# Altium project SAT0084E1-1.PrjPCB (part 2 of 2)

## Sheet SAT0084E1-1_Backend.SchDoc: Class-D Amplifier
size 431 x 279 mm; Date: Not shown in title block; ApprovedBy: Not shown in title block; CheckedBy: Not shown in title block; Author: Not shown in title block; CompanyName: Not shown in title block; DrawnBy: Viktor Schneigelberger; Engineer: Not shown in title block; Organization: Not shown in title block; Address1: Not shown in title block; Address2: Not shown in title block; Address3: Not shown in title block; Address4: Not shown in title block; DocumentNumber: 6; Revision: Use project parameter SCH_Rev; SheetNumber: 6; SheetTotal: 7; PageSetup: Record=PageOptions|CenterHorizontal=True|CenterVertical=True|PrintScale=1.00|XCorrection=1.00|YCorrection=1.00|PrintKind=0|BorderSize=5000000|LeftOffset=0|BottomOffset=0|Orientation=2|PaperLength=1000|PaperWidth=1000|Scale=100|PaperSource=15|PrintQuality=600|MediaType=1|DitherType=10|PaperKind=Letter|PrintScaleMode=1
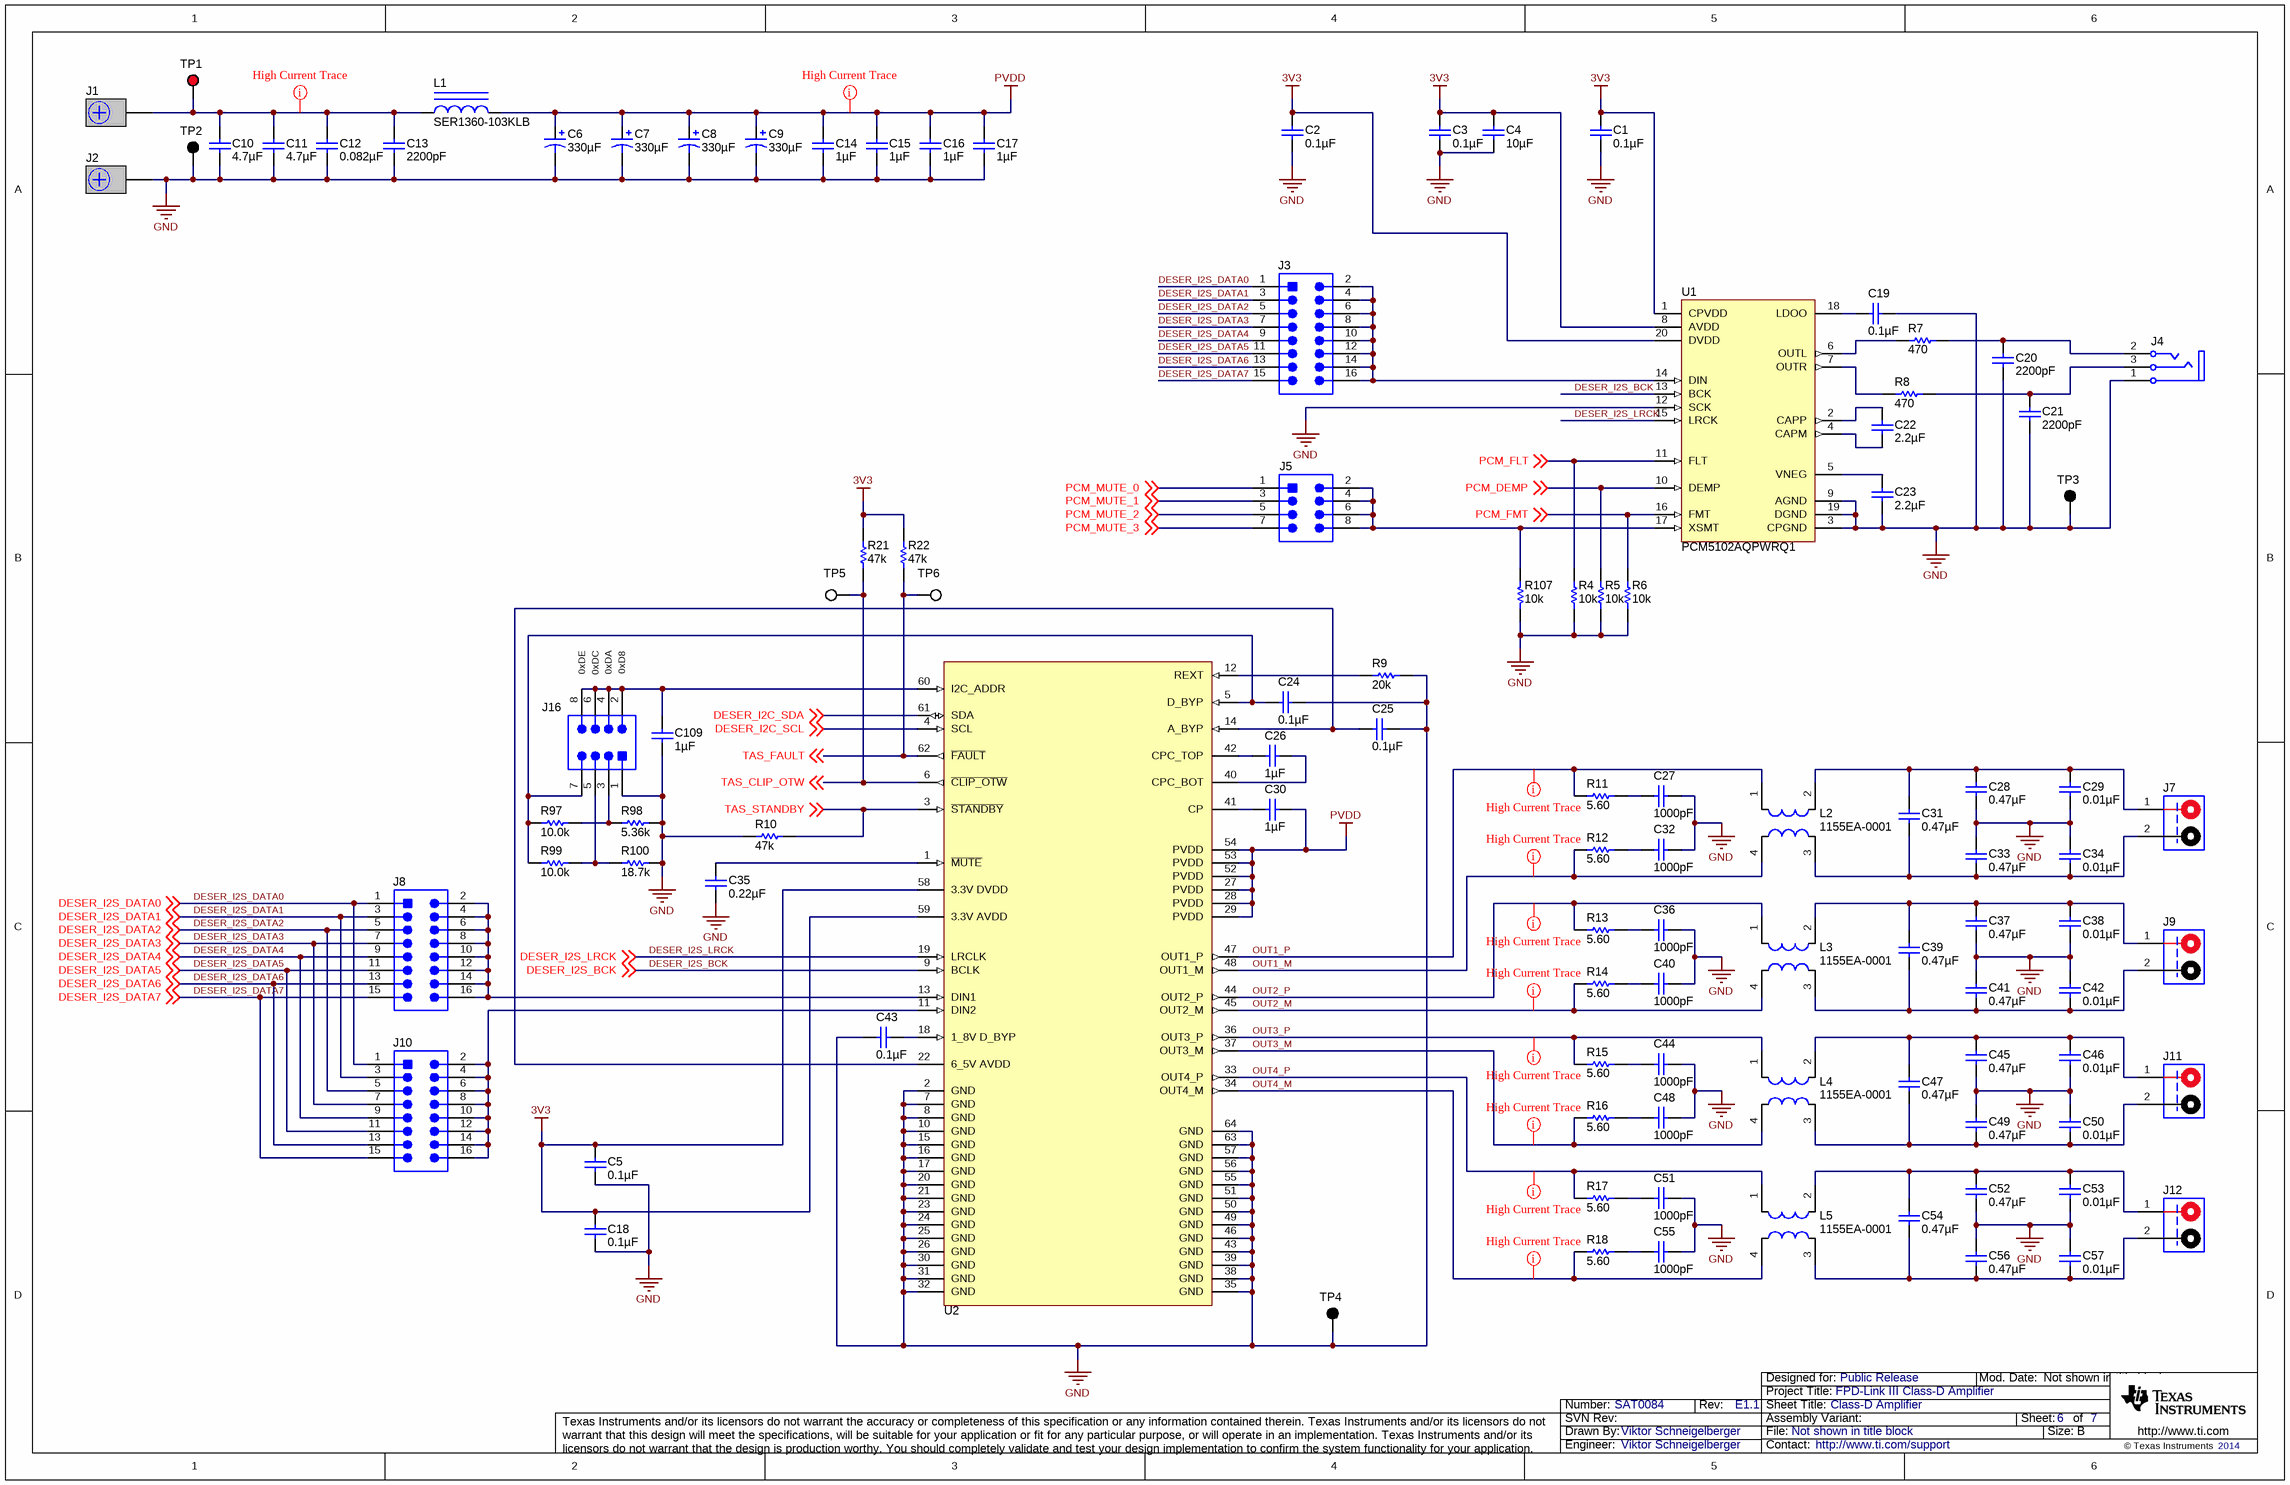
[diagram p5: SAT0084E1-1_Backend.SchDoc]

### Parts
C1  ValueDisplayed: 0.1µF  [0402]  (hidden comment: GRM155R71A104KA01D)
C2  ValueDisplayed: 0.1µF  [0402]  (hidden comment: GRM155R71A104KA01D)
C3  ValueDisplayed: 0.1µF  [0402]  (hidden comment: GRM155R71A104KA01D)
C4  ValueDisplayed: 10µF  [0805_HV]  (hidden comment: GRM21BR71A106KE51L)
C5  ValueDisplayed: 0.1µF  [0402]  (hidden comment: GRM155R71A104KA01D)
C6  ValueDisplayed: 330µF  [SM_RADIAL_H13]  (hidden comment: EEV-FK1H331Q)
C7  ValueDisplayed: 330µF  [SM_RADIAL_H13]  (hidden comment: EEV-FK1H331Q)
C8  ValueDisplayed: 330µF  [SM_RADIAL_H13]  (hidden comment: EEV-FK1H331Q)
C9  ValueDisplayed: 330µF  [SM_RADIAL_H13]  (hidden comment: EEV-FK1H331Q)
C10  ValueDisplayed: 4.7µF  [1206]  (hidden comment: GRM31CR71H475KA12L)
C11  ValueDisplayed: 4.7µF  [1206]  (hidden comment: GRM31CR71H475KA12L)
C12  ValueDisplayed: 0.082µF  [0603]  (hidden comment: GRM188R71H823KA93D)
C13  ValueDisplayed: 2200pF  [0603]  (hidden comment: GRM188R71H222KA01D)
C14  ValueDisplayed: 1µF  [0603]  (hidden comment: GRM188R71E105KA12D)
C15  ValueDisplayed: 1µF  [0603]  (hidden comment: GRM188R71E105KA12D)
C16  ValueDisplayed: 1µF  [0603]  (hidden comment: GRM188R71E105KA12D)
C17  ValueDisplayed: 1µF  [0603]  (hidden comment: GRM188R71E105KA12D)
C18  ValueDisplayed: 0.1µF  [0402]  (hidden comment: GRM155R71A104KA01D)
C19  ValueDisplayed: 0.1µF  [0402]  (hidden comment: GRM155R71A104KA01D)
C20  ValueDisplayed: 2200pF  [0402]  (hidden comment: GRM155R71C222KA01D)
C21  ValueDisplayed: 2200pF  [0402]  (hidden comment: GRM155R71C222KA01D)
C22  ValueDisplayed: 2.2µF  [0603]  (hidden comment: GRM188R71A225KE15D)
C23  ValueDisplayed: 2.2µF  [0603]  (hidden comment: GRM188R71A225KE15D)
C24  ValueDisplayed: 0.1µF  [0402]  (hidden comment: GRM155R71A104KA01D)
C25  ValueDisplayed: 0.1µF  [0402]  (hidden comment: GRM155R71A104KA01D)
C26  ValueDisplayed: 1µF  [0805_HV]  (hidden comment: GRM21BR71H105KA12L)
C27  ValueDisplayed: 1000pF  [0603]  (hidden comment: C0603C102J5RACTU)
C28  ValueDisplayed: 0.47µF  [0805_HV]  (hidden comment: GRM21BR71H474KA88L)
C29  ValueDisplayed: 0.01µF  [0603]  (hidden comment: C0603C103J5RACTU)
C30  ValueDisplayed: 1µF  [0805_HV]  (hidden comment: GRM21BR71H105KA12L)
C31  ValueDisplayed: 0.47µF  [0805_HV]  (hidden comment: GRM21BR71H474KA88L)
C32  ValueDisplayed: 1000pF  [0603]  (hidden comment: C0603C102J5RACTU)
C33  ValueDisplayed: 0.47µF  [0805_HV]  (hidden comment: GRM21BR71H474KA88L)
C34  ValueDisplayed: 0.01µF  [0603]  (hidden comment: C0603C103J5RACTU)
C35  ValueDisplayed: 0.22µF  [0402]  (hidden comment: GRM155R71C224KA12D)
C36  ValueDisplayed: 1000pF  [0603]  (hidden comment: C0603C102J5RACTU)
C37  ValueDisplayed: 0.47µF  [0805_HV]  (hidden comment: GRM21BR71H474KA88L)
C38  ValueDisplayed: 0.01µF  [0603]  (hidden comment: C0603C103J5RACTU)
C39  ValueDisplayed: 0.47µF  [0805_HV]  (hidden comment: GRM21BR71H474KA88L)
C40  ValueDisplayed: 1000pF  [0603]  (hidden comment: C0603C102J5RACTU)
C41  ValueDisplayed: 0.47µF  [0805_HV]  (hidden comment: GRM21BR71H474KA88L)
C42  ValueDisplayed: 0.01µF  [0603]  (hidden comment: C0603C103J5RACTU)
C43  ValueDisplayed: 0.1µF  [0402]  (hidden comment: GRM155R71A104KA01D)
C44  ValueDisplayed: 1000pF  [0603]  (hidden comment: C0603C102J5RACTU)
C45  ValueDisplayed: 0.47µF  [0805_HV]  (hidden comment: GRM21BR71H474KA88L)
C46  ValueDisplayed: 0.01µF  [0603]  (hidden comment: C0603C103J5RACTU)
C47  ValueDisplayed: 0.47µF  [0805_HV]  (hidden comment: GRM21BR71H474KA88L)
C48  ValueDisplayed: 1000pF  [0603]  (hidden comment: C0603C102J5RACTU)
C49  ValueDisplayed: 0.47µF  [0805_HV]  (hidden comment: GRM21BR71H474KA88L)
C50  ValueDisplayed: 0.01µF  [0603]  (hidden comment: C0603C103J5RACTU)
C51  ValueDisplayed: 1000pF  [0603]  (hidden comment: C0603C102J5RACTU)
C52  ValueDisplayed: 0.47µF  [0805_HV]  (hidden comment: GRM21BR71H474KA88L)
C53  ValueDisplayed: 0.01µF  [0603]  (hidden comment: C0603C103J5RACTU)
C54  ValueDisplayed: 0.47µF  [0805_HV]  (hidden comment: GRM21BR71H474KA88L)
C55  ValueDisplayed: 1000pF  [0603]  (hidden comment: C0603C102J5RACTU)
C56  ValueDisplayed: 0.47µF  [0805_HV]  (hidden comment: GRM21BR71H474KA88L)
C57  ValueDisplayed: 0.01µF  [0603]  (hidden comment: C0603C103J5RACTU)
C109  ValueDisplayed: 1µF  [0603]  (hidden comment: GRM188R71A105KA61D)
J1  24V  [CB35-36-CY]  (value not drawn)
J2  GND  [CB35-36-CY]  (value not drawn)
J3  DIN PCM  [Samtec_FTS-108-02-x-DV]  (value not drawn)
J4  SJ-3523-SMT  [CUI_SJ-3523-SMT]  (value not drawn)
J5  Mute PCM  [Samtec_FTS-104-02-x-DV]  (value not drawn)
J7  CH1  [CONN_POMONA_2269-0]  (value not drawn)
J8  DIN1 TAS  [Samtec_FTS-108-02-x-DV]  (value not drawn)
J9  CH2  [CONN_POMONA_2269-0]  (value not drawn)
J10  DIN2 TAS  [Samtec_FTS-108-02-x-DV]  (value not drawn)
J11  CH3  [CONN_POMONA_2269-0]  (value not drawn)
J12  CH4  [CONN_POMONA_2269-0]  (value not drawn)
J16  Addr TAS  [Samtec_FTS-104-02-x-DV]  (value not drawn)
L1  SER1360-103KLB  [SER1360]
L2  1155EA-0001  [HEAW]
L3  1155EA-0001  [HEAW]
L4  1155EA-0001  [HEAW]
L5  1155EA-0001  [HEAW]
R4  value 10k  [0402]  (hidden comment: CRCW040210K0JNED)
R5  value 10k  [0402]  (hidden comment: CRCW040210K0JNED)
R6  value 10k  [0402]  (hidden comment: CRCW040210K0JNED)
R7  value 470  [0402]  (hidden comment: CRCW0402470RJNED)
R8  value 470  [0402]  (hidden comment: CRCW0402470RJNED)
R9  value 20k  [0402]  (hidden comment: CRCW040220K0JNED)
R10  value 47k  [0402]  (hidden comment: CRCW040247K0JNED)
R11  value 5.60  [0805_HV]  (hidden comment: RL1220S-5.6-F)
R12  value 5.60  [0805_HV]  (hidden comment: RL1220S-5.6-F)
R13  value 5.60  [0805_HV]  (hidden comment: RL1220S-5.6-F)
R14  value 5.60  [0805_HV]  (hidden comment: RL1220S-5.6-F)
R15  value 5.60  [0805_HV]  (hidden comment: RL1220S-5.6-F)
R16  value 5.60  [0805_HV]  (hidden comment: RL1220S-5.6-F)
R17  value 5.60  [0805_HV]  (hidden comment: RL1220S-5.6-F)
R18  value 5.60  [0805_HV]  (hidden comment: RL1220S-5.6-F)
R21  value 47k  [0402]  (hidden comment: CRCW040247K0JNED)
R22  value 47k  [0402]  (hidden comment: CRCW040247K0JNED)
R97  value 10.0k  [0402]  (hidden comment: CRCW040210K0FKED)
R98  value 5.36k  [0402]  (hidden comment: CRCW04025K36FKED)
R99  value 10.0k  [0402]  (hidden comment: CRCW040210K0FKED)
R100  value 18.7k  [0402]  (hidden comment: CRCW040218K7FKED)
R107  value 10k  [0402]  (hidden comment: CRCW040210K0JNED)
TP1  24V  [Keystone5005]  (value not drawn)
TP2  GND  [Keystone5006]  (value not drawn)
TP3  GND  [Keystone5006]  (value not drawn)
TP4  GND  [Keystone5006]  (value not drawn)
TP5  CLIP_OTW  [Keystone5007]  (value not drawn)
TP6  FAULT  [Keystone5007]  (value not drawn)
U1  PCM5102AQPWRQ1  [PW0020A_N]
U2  *  [PBH0064A_n]  (value not drawn)

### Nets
3V3: C1.1 C2.1 C3.1 C4.1 C5.1 C18.1 R21.2 R22.2 U1.1(CPVDD) U1.8(AVDD) U1.20(DVDD) U2.58(3.3V_DVDD) U2.59(3.3V_AVDD)
GND: C1.2 C2.2 C3.2 C4.2 C5.2 C6.2(-) C7.2(-) C8.2(-) C9.2(-) C10.2 C11.2 C12.2 C13.2 C14.2 C15.2 C16.2 C17.2 C18.2 C19.1 C20.2 C21.2 C23.2 C24.2 C25.2 C27.1 C28.2 C29.2 C32.1 C33.1 C34.1 C35.2 C36.1 C37.2 C38.2 C40.1 C41.1 C42.1 C43.1 C44.1 C45.2 C46.2 C48.1 C49.1 C50.1 C51.1 C52.2 C53.2 C55.1 C56.1 C57.1 C109.2 J2.1 J4.1(S) J16.1 R4.1 R5.1 R6.1 R9.2 R10.2 R98.2 R100.2 R107.1 TP2.1 TP3.1 TP4.1 U1.3(CPGND) U1.9(AGND) U1.12(SCK) U1.19(DGND) U2.2(GND) U2.7(GND) U2.8(GND) U2.10(GND) U2.15(GND) U2.16(GND) U2.17(GND) U2.20(GND) U2.21(GND) U2.23(GND) U2.24(GND) U2.25(GND) U2.26(GND) U2.30(GND) U2.31(GND) U2.32(GND) U2.35(GND) U2.38(GND) U2.39(GND) U2.43(GND) U2.46(GND) U2.49(GND) U2.50(GND) U2.51(GND) U2.55(GND) U2.56(GND) U2.57(GND) U2.63(GND) U2.64(GND)
PVDD: C6.1(+) C7.1(+) C8.1(+) C9.1(+) C14.1 C15.1 C16.1 C17.1 C30.1 L1.2 U2.27(PVDD) U2.28(PVDD) U2.29(PVDD) U2.52(PVDD) U2.53(PVDD) U2.54(PVDD)
DESER_I2C_SCL: U2.4(SCL) ; off-sheet DESER_I2C_SCL
DESER_I2C_SDA: U2.61(SDA) ; off-sheet DESER_I2C_SDA
DESER_I2S_BCK: U1.13(BCK) U2.9(BCLK) ; off-sheet DESER_I2S_BCK
DESER_I2S_DATA0: J3.1 J8.1 J10.1 ; off-sheet DESER_I2S_DATA0
DESER_I2S_DATA1: J3.3 J8.3 J10.3 ; off-sheet DESER_I2S_DATA1
DESER_I2S_DATA2: J3.5 J8.5 J10.5 ; off-sheet DESER_I2S_DATA2
DESER_I2S_DATA3: J3.7 J8.7 J10.7 ; off-sheet DESER_I2S_DATA3
DESER_I2S_DATA4: J3.9 J8.9 J10.9 ; off-sheet DESER_I2S_DATA4
DESER_I2S_DATA5: J3.11 J8.11 J10.11 ; off-sheet DESER_I2S_DATA5
DESER_I2S_DATA6: J3.13 J8.13 J10.13 ; off-sheet DESER_I2S_DATA6
DESER_I2S_DATA7: J3.15 J8.15 J10.15 ; off-sheet DESER_I2S_DATA7
DESER_I2S_LRCK: U1.15(LRCK) U2.19(LRCLK) ; off-sheet DESER_I2S_LRCK
OUT1_M: L2.4 R12.1 U2.48(OUT1_M)
OUT1_P: L2.1 R11.1 U2.47(OUT1_P)
OUT2_M: L3.4 R14.1 U2.45(OUT2_M)
OUT2_P: L3.1 R13.1 U2.44(OUT2_P)
OUT3_M: L4.4 R16.1 U2.37(OUT3_M)
OUT3_P: L4.1 R15.1 U2.36(OUT3_P)
OUT4_M: L5.4 R18.1 U2.34(OUT4_M)
OUT4_P: L5.1 R17.1 U2.33(OUT4_P)
PCM_DEMP: R5.2 U1.10(DEMP) ; off-sheet PCM_DEMP
PCM_FLT: R4.2 U1.11(FLT) ; off-sheet PCM_FLT
PCM_FMT: R6.2 U1.16(FMT) ; off-sheet PCM_FMT
PCM_MUTE_0: J5.1 ; off-sheet PCM_MUTE_0
PCM_MUTE_1: J5.3 ; off-sheet PCM_MUTE_1
PCM_MUTE_2: J5.5 ; off-sheet PCM_MUTE_2
PCM_MUTE_3: J5.7 ; off-sheet PCM_MUTE_3
TAS_CLIP_OTW: R21.1 TP5.1 U2.6(~{CLIP_OTW}) ; off-sheet TAS_CLIP_OTW
TAS_FAULT: R22.1 TP6.1 U2.62(~{FAULT}) ; off-sheet TAS_FAULT
TAS_STANDBY: R10.1 U2.3(~{STANDBY}) ; off-sheet TAS_STANDBY
NetC10_1: C10.1 C11.1 C12.1 C13.1 J1.1 L1.1 TP1.1
NetC19_2: C19.2 U1.18(LDOO)
NetC20_1: C20.1 J4.2(L) R7.2
NetC21_1: C21.1 J4.3(R) R8.2
NetC22_1: C22.1 U1.2(CAPP)
NetC22_2: C22.2 U1.4(CAPM)
NetC23_1: C23.1 U1.5(VNEG)
NetC24_1: C24.1 J16.7 R97.1 R99.1 U2.5(D_BYP)
NetC25_1: C25.1 U2.14(A_BYP) U2.22(6_5V_AVDD)
NetC26_1: C26.1 U2.42(CPC_TOP)
NetC26_2: C26.2 U2.40(CPC_BOT)
NetC27_2: C27.2 R11.2
NetC28_1: C28.1 C29.1 C31.1 J7.1 L2.2
NetC30_2: C30.2 U2.41(CP)
NetC31_2: C31.2 C33.2 C34.2 J7.2 L2.3
NetC32_2: C32.2 R12.2
NetC35_1: C35.1 U2.1(~{MUTE})
NetC36_2: C36.2 R13.2
NetC37_1: C37.1 C38.1 C39.1 J9.1 L3.2
NetC39_2: C39.2 C41.2 C42.2 J9.2 L3.3
NetC40_2: C40.2 R14.2
NetC43_2: C43.2 U2.18(1_8V_D_BYP)
NetC44_2: C44.2 R15.2
NetC45_1: C45.1 C46.1 C47.1 J11.1 L4.2
NetC47_2: C47.2 C49.2 C50.2 J11.2 L4.3
NetC48_2: C48.2 R16.2
NetC51_2: C51.2 R17.2
NetC52_1: C52.1 C53.1 C54.1 J12.1 L5.2
NetC54_2: C54.2 C56.2 C57.2 J12.2 L5.3
NetC55_2: C55.2 R18.2
NetC109_1: C109.1 J16.2 J16.4 J16.6 J16.8 U2.60(I2C_ADDR)
NetJ3_2: J3.2 J3.4 J3.6 J3.8 J3.10 J3.12 J3.14 J3.16 U1.14(DIN)
NetJ5_2: J5.2 J5.4 J5.6 J5.8 R107.2 U1.17(XSMT)
NetJ8_2: J8.2 J8.4 J8.6 J8.8 J8.10 J8.12 J8.14 J8.16 U2.13(DIN1)
NetJ10_2: J10.2 J10.4 J10.6 J10.8 J10.10 J10.12 J10.14 J10.16 U2.11(DIN2)
NetJ16_3: J16.3 R97.2 R98.1
NetJ16_5: J16.5 R99.2 R100.1
NetR7_1: R7.1 U1.6(OUTL)
NetR8_1: R8.1 U1.7(OUTR)
NetR9_1: R9.1 U2.12(REXT)

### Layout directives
mark named High Current Trace: NetC10_1, OUT1_M, OUT1_P, OUT2_M, OUT2_P, OUT3_M, OUT3_P, OUT4_M, OUT4_P, PVDD

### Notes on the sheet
- (near J16) 0xDE
- (near J16) 0xDC
- (near J16) 0xDA
- 0xD8

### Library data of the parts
C1-C3 C5 C18 C19 C24 C25 C43 = GRM155R71A104KA01D: CAP, CERM, 0.1uF, 10V, +/-10%, X7R, 0402; Manufacturer: MuRata; Polarized: N; CompType: Capacitor; U/M: EA; Cap_F: 0.0000001; Tolerance_%: 10; Value1: Unknown; TaMin_C: -55; TaMax_C: 125
C4 = GRM21BR71A106KE51L: CAP, CERM, 10uF, 10V, +/-10%, X7R, 0805; Manufacturer: MuRata; Polarized: N; CompType: Capacitor; U/M: EA; Cap_F: 0.00001; Tolerance_%: 10; ESR_Ohm: 0.003; Value1: 0.003 ohm; TaMin_C: -55; TaMax_C: 125; Cap_Case: 0805
C6-C9 = EEV-FK1H331Q: CAP, AL, 330uF, 50V, +/-20%, 0.12 ohm, SMD; Manufacturer: Panasonic; Polarized: Y; CompType: Capacitor; U/M: EA; Cap_F: 0.00033; Tolerance_%: 20; VDC_V: 50; ESR_Ohm: 0.12; IRMS_A: 0.9; TaMin_C: -55; TaMax_C: 105; Cap_Case: H13
C10 C11 = GRM31CR71H475KA12L: CAP, CERM, 4.7uF, 50V, +/-10%, X7R, 1206; Manufacturer: MuRata; Polarized: N; CompType: Capacitor; U/M: EA; Cap_F: 0.0000047; Tolerance_%: 10; Value1: Unknown; VDC_V: 50; TaMin_C: -55; TaMax_C: 125; Cap_Case: 2220
C12 = GRM188R71H823KA93D: CAP, CERM, 0.082uF, 50V, +/-10%, X7R, 0603; Manufacturer: MuRata; Polarized: N; CompType: Capacitor; U/M: EA; Cap_F: 0.000000082; Tolerance_%: 10; Value1: Unknown; VDC_V: 50; TaMin_C: -55; TaMax_C: 125
C13 = GRM188R71H222KA01D: CAP, CERM, 2200pF, 50V, +/-10%, X7R, 0603; Manufacturer: MuRata; Polarized: N; CompType: Capacitor; U/M: EA; Cap_F: 0.0000000022; Tolerance_%: 10; Value1: Unknown; VDC_V: 50; TaMin_C: -55; TaMax_C: 125
C14-C17 = GRM188R71E105KA12D: CAP, CERM, 1uF, 25V, +/-10%, X7R, 0603; Manufacturer: MuRata; Polarized: N; CompType: Capacitor; U/M: EA; Cap_F: 0.000001; Tolerance_%: 10; Value1: Unknown; VDC_V: 25; TaMin_C: -55; TaMax_C: 125
C20 C21 = GRM155R71C222KA01D: CAP, CERM, 2200pF, 16V, +/-10%, X7R, 0402; Manufacturer: MuRata; Polarized: N; CompType: Capacitor; U/M: EA; Cap_F: 0.0000000022; Tolerance_%: 10; Value1: Unknown; VDC_V: 16; TaMin_C: -55; TaMax_C: 125
C22 C23 = GRM188R71A225KE15D: CAP, CERM, 2.2uF, 10V, +/-10%, X7R, 0603; Manufacturer: MuRata; Polarized: N; CompType: Capacitor; U/M: EA; Cap_F: 0.0000022; Tolerance_%: 10; ESR_Ohm: 0.009; Value1: 0.009 ohm; TaMin_C: -55; TaMax_C: 125
C26 C30 = GRM21BR71H105KA12L: CAP, CERM, 1uF, 50V, +/-10%, X7R, 0805; Manufacturer: MuRata; Polarized: N; CompType: Capacitor; U/M: EA; Cap_F: 0.000001; Tolerance_%: 10; Value1: Unknown; VDC_V: 50; TaMin_C: -55; TaMax_C: 125; Cap_Case: 0805
C27 C32 C36 C40 C44 C48 C51 C55 = C0603C102J5RACTU: CAP, CERM, 1000pF, 50V, +/-5%, X7R, 0603; Manufacturer: Kemet; Polarized: N; CompType: Capacitor; U/M: EA; Cap_F: 0.000000001; Tolerance_%: 5; Value1: Unknown; VDC_V: 50; TaMin_C: -55; TaMax_C: 125
C28 C31 C33 C37 C39 C41 C45 C47 C49 C52 C54 C56 = GRM21BR71H474KA88L: CAP, CERM, 0.47uF, 50V, +/-10%, X7R, 0805; Manufacturer: MuRata; Polarized: N; CompType: Capacitor; U/M: EA; Cap_F: 0.00000047; Tolerance_%: 10; Value1: Unknown; VDC_V: 50; TaMin_C: -55; TaMax_C: 125; Cap_Case: 0805
C29 C34 C38 C42 C46 C50 C53 C57 = C0603C103J5RACTU: CAP, CERM, 0.01uF, 50V, +/-5%, X7R, 0603; Manufacturer: Kemet; Polarized: N; CompType: Capacitor; U/M: EA; Cap_F: 0.00000001; Tolerance_%: 5; Value1: Unknown; VDC_V: 50; TaMin_C: -55; TaMax_C: 125
C35 = GRM155R71C224KA12D: CAP, CERM, 0.22uF, 16V, +/-10%, X7R, 0402; Manufacturer: MuRata; Polarized: N; CompType: Capacitor; U/M: EA; Cap_F: 0.00000022; Tolerance_%: 10; Value1: Unknown; VDC_V: 16; TaMin_C: -55; TaMax_C: 125
C109 = GRM188R71A105KA61D: CAP, CERM, 1uF, 10V, +/-10%, X7R, 0603; Manufacturer: MuRata; Polarized: N; CompType: Capacitor; U/M: EA; Cap_F: 0.000001; Tolerance_%: 10; ESR_Ohm: 0.011; Value1: 0.011 ohm; TaMin_C: -55; TaMax_C: 125
J1 J2 = CB35-36-CY: Terminal 50A Lug; Manufacturer: Panduit; CompType: Screw Terminal; SymbolCreator: crossc; U/M: EA
J3 J8 J10 = FTS-108-02-L-DV: Header, 8x2, 1.27mm; Manufacturer: Samtec; SymbolCreator: a0412235; U/M: EA
J4 = SJ-3523-SMT: Connector, Audio Jack, 3.5mm, Stereo, SMD; Manufacturer: CUI Inc.; SymbolCreator: codlsc; U/M: EA
J5 J16 = FTS-104-02-L-DV: Header, 4x2, 1.27mm; Manufacturer: Samtec; SymbolCreator: a0411947; U/M: EA
J7 J9 J11 J12 = 2269-0: Connector, Banana Jack, Double, Black Base, 15A, TH; PartNumber: 6883; Manufacturer: Pomona Electronics; SymbolCreator: a0799721; U/M: EA
L1 = SER1360-103KLB: Inductor, Shielded E Core, Ferrite, 10uH, 7.2A, 0.01 ohm, SMD; Manufacturer: Coilcraft; Ind_H: 10.0E-6; ValueDisplayed: 10µH; Imax_A: 7.2; Irms: 7.2A @ 40C rise; Isat: 7.5A @ 30% inductance drop; DCR_ohm: 0.01; U/M: EA
L2-L5 = 1155EA-0001: Inductor, Shielded, Ferrite, 10uH, 3A, 0.022 ohm, SMD; Manufacturer: Toko; SymbolCreator: a0412235; Ind_H: 10.0E-6; ValueDisplayed: 10µH; Imax_A: 3; Irms: 3A @ 40C rise; Isat: 4.2A @ 10% inductance drop; DCR_ohm: 0.022; U/M: EA
R4-R6 R107 = CRCW040210K0JNED: RES, 10k ohm, 5%, 0.063W, 0402; Manufacturer: Vishay-Dale; CompType: Resistor; Res_ohm: 10000; Value_Code: 10k0; Tolerance_%: 5; Power_W: 0.063; VDC_V: 50; TempCo: 200 ppm/C; EIA_Code: E24; U/M: EA
R7 R8 = CRCW0402470RJNED: RES, 470 ohm, 5%, 0.063W, 0402; Manufacturer: Vishay-Dale; CompType: Resistor; Value_Code: 470R; Tolerance_%: 5; Power_W: 0.063; VDC_V: 50; TempCo: 200 ppm/C; EIA_Code: E24; U/M: EA
R9 = CRCW040220K0JNED: RES, 20k ohm, 5%, 0.063W, 0402; Manufacturer: Vishay-Dale; CompType: Resistor; Tolerance_%: 5; VDC_V: 50; TempCo: 200 ppm/C; U/M: EA; Res_ohm: 20000; Value_Code: 20k0; Power_W: 0.063; EIA_Code: E24
R10 R21 R22 = CRCW040247K0JNED: RES, 47k ohm, 5%, 0.063W, 0402; Manufacturer: Vishay-Dale; CompType: Resistor; Res_ohm: 47000; Value_Code: 47k0; Tolerance_%: 5; Power_W: 0.063; VDC_V: 50; TempCo: 200 ppm/C; EIA_Code: E24; U/M: EA
R11-R18 = RL1220S-5.6-F: RES, 5.60 ohm, 1%, 0.33W, 0805; Manufacturer: Susumu Co Ltd; CompType: Resistor; Res_ohm: 5.6; Value_Code: 5R60; Tolerance_%: 1; Power_W: 0.33; TempCo: 200 ppm/C; U/M: EA
R97 R99 = CRCW040210K0FKED: RES, 10.0k ohm, 1%, 0.063W, 0402; Manufacturer: Vishay-Dale; CompType: Resistor; Res_ohm: 10000; Value_Code: 10k0; Tolerance_%: 1; Power_W: 0.063; VDC_V: 50; TempCo: 100 ppm/C; EIA_Code: E96; U/M: EA
R98 = CRCW04025K36FKED: RES, 5.36k ohm, 1%, 0.063W, 0402; Manufacturer: Vishay-Dale; CompType: Resistor; Res_ohm: 5360; Value_Code: 5k36; Tolerance_%: 1; Power_W: 0.063; VDC_V: 50; TempCo: 100 ppm/C; EIA_Code: E96; U/M: EA
R100 = CRCW040218K7FKED: RES, 18.7k ohm, 1%, 0.063W, 0402; Manufacturer: Vishay-Dale; CompType: Resistor; Res_ohm: 18700; Value_Code: 18k7; Tolerance_%: 1; Power_W: 0.063; VDC_V: 50; TempCo: 100 ppm/C; EIA_Code: E96; U/M: EA
TP1 = 5005: Test Point, Compact, Red, TH; Manufacturer: Keystone; CompType: Test Point Loop; U/M: EA
TP2-TP4 = 5006: Test Point, Compact, Black, TH; Manufacturer: Keystone; CompType: Test Point Loop; U/M: EA
TP5 TP6 = 5007: Test Point, Compact, White, TH; Manufacturer: Keystone; CompType: Test Point Loop; U/M: EA
U1 = PCM5102AQPWRQ1: 2-VRMS DirectPath™, 112, 106, 100-dB Audio Stereo DAC with 32-bit, 384-kHz PCM Interface, PW0020A; Alternate Manufacturer: None; Manufacturer: Texas Instruments; SymbolCreator: x0208326; CompType: IC; U/M: EA
U2 = Digital Input Four-Channel Automotive Digital Amplifier: There is nothing to buy or mount.; Manufacturer: TI; CompType: Used in some BOM reports.  Useful for finding later.

## Sheet SAT0084E1-1_Hardware.SchDoc: Hardware
size 431 x 279 mm; Date: Not shown in title block; ApprovedBy: Not shown in title block; CheckedBy: Not shown in title block; Author: Not shown in title block; CompanyName: Not shown in title block; DrawnBy: Viktor Schneigelberger; Engineer: Not shown in title block; Organization: Not shown in title block; Address1: Not shown in title block; Address2: Not shown in title block; Address3: Not shown in title block; Address4: Not shown in title block; DocumentNumber: 2; Revision: Use project parameter SCH_Rev; SheetNumber: 7; SheetTotal: 7; PageSetup: Record=PageOptions|CenterHorizontal=True|CenterVertical=True|PrintScale=1.00|XCorrection=1.00|YCorrection=1.00|PrintKind=0|BorderSize=5000000|LeftOffset=0|BottomOffset=0|Orientation=2|PaperLength=1000|PaperWidth=1000|Scale=100|PaperSource=15|PrintQuality=600|MediaType=1|DitherType=10|PaperKind=Letter|PrintScaleMode=1
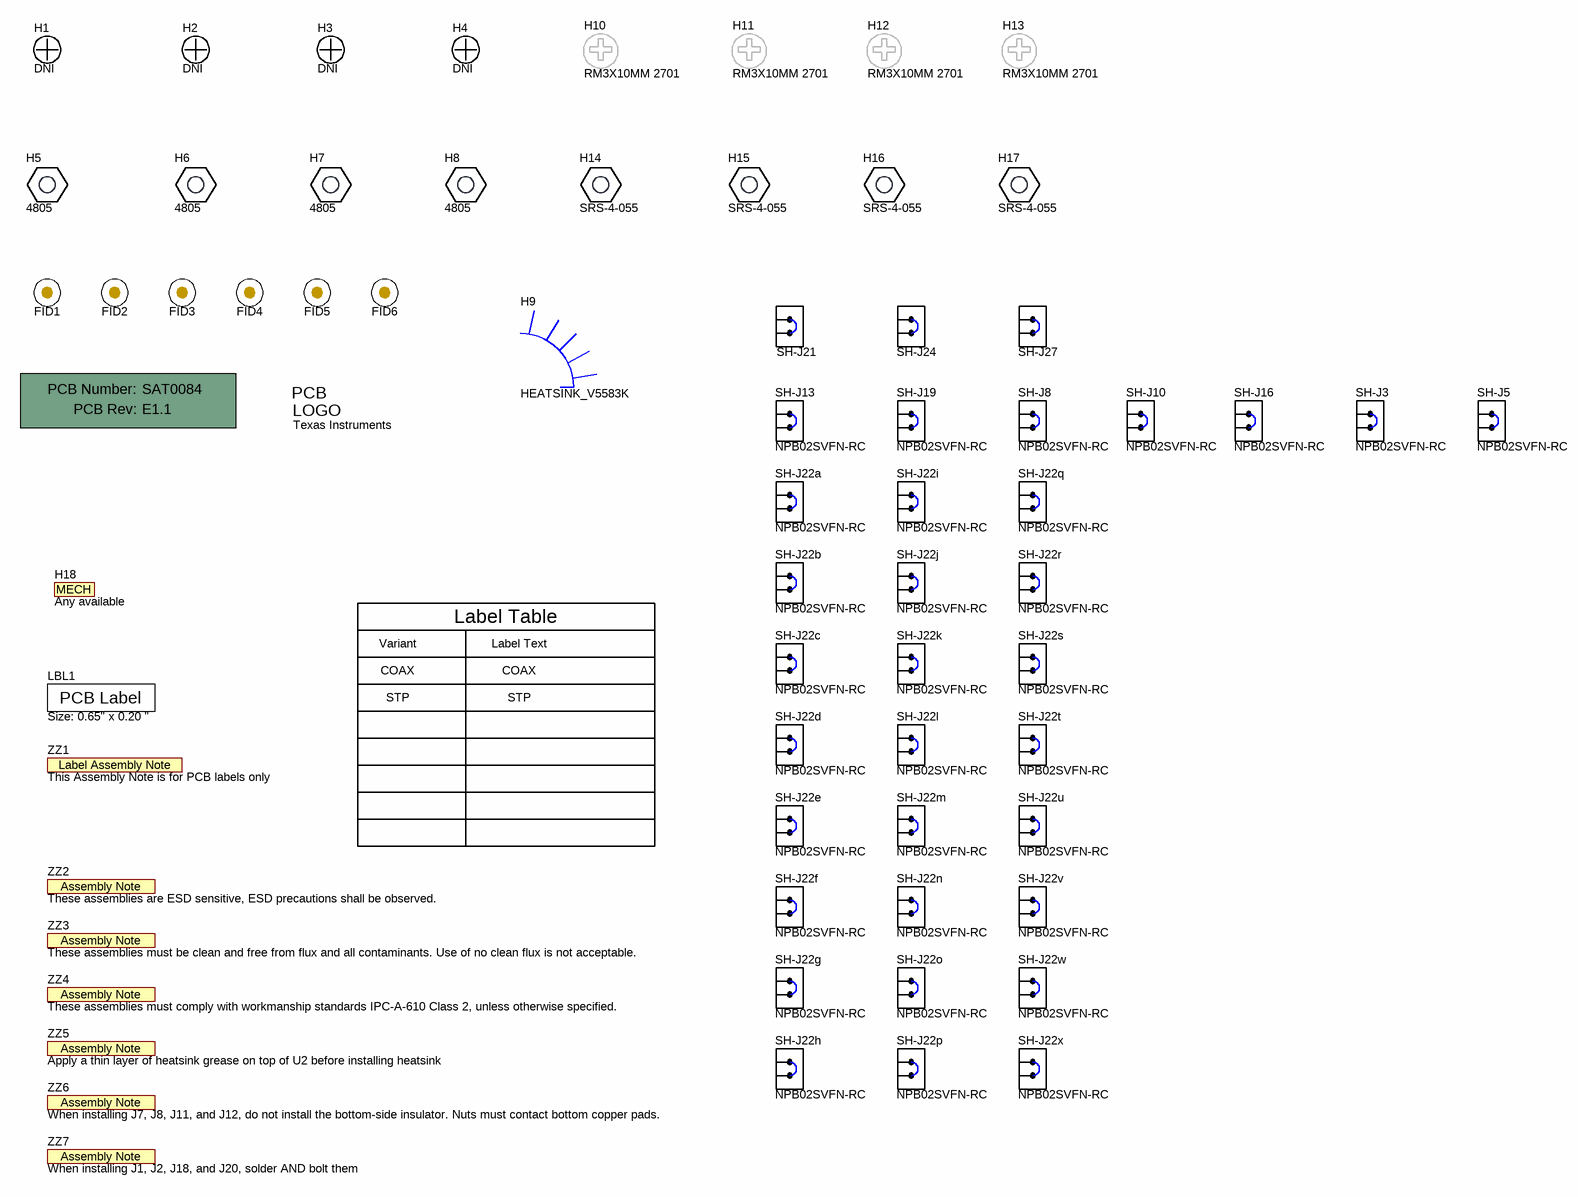
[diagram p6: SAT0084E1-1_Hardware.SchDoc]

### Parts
!PCB1  Printed Circuit Board  (value not drawn)  (mechanical)
FID1  Fiducial  [Fiducial10-20]  (value not drawn)
FID2  Fiducial  [Fiducial10-20]  (value not drawn)
FID3  Fiducial  [Fiducial10-20]  (value not drawn)
FID4  Fiducial  [Fiducial10-20]  (value not drawn)
FID5  Fiducial  [Fiducial10-20]  (value not drawn)
FID6  Fiducial  [Fiducial10-20]  (value not drawn)
H1  DNI  [NY PMS 440 0025 PH]
H2  DNI  [NY PMS 440 0025 PH]
H3  DNI  [NY PMS 440 0025 PH]
H4  DNI  [NY PMS 440 0025 PH]
H5  4805  [Keystone_1902C]
H6  4805  [Keystone_1902C]
H7  4805  [Keystone_1902C]
H8  4805  [Keystone_1902C]
H9  HEATSINK_V5583K  [HEATSINK_V5583K]
H10  RM3X10MM 2701  [BuildingFastener_MPMS_003_0005_PH]
H11  RM3X10MM 2701  [BuildingFastener_MPMS_003_0005_PH]
H12  RM3X10MM 2701  [BuildingFastener_MPMS_003_0005_PH]
H13  RM3X10MM 2701  [BuildingFastener_MPMS_003_0005_PH]
H14  SRS-4-055  [Keystone_1902C]
H15  SRS-4-055  [Keystone_1902C]
H16  SRS-4-055  [Keystone_1902C]
H17  SRS-4-055  [Keystone_1902C]
H18  Any available  (mechanical)
LBL1  Size: 0.65" x 0.20 "  [Label_650x200]
Logo1  Texas Instruments  [TI_Stacked_SolderMask_Small]  (no BOM)
SH-J3  NPB02SVFN-RC  [NPB02SVFN-RC]
SH-J5  NPB02SVFN-RC  [NPB02SVFN-RC]
SH-J8  NPB02SVFN-RC  [NPB02SVFN-RC]
SH-J10  NPB02SVFN-RC  [NPB02SVFN-RC]
SH-J13  NPB02SVFN-RC  [NPB02SVFN-RC]
SH-J16  NPB02SVFN-RC  [NPB02SVFN-RC]
SH-J19  NPB02SVFN-RC  [NPB02SVFN-RC]
SH-J21  969102-0000-DA  [SNT-100-BK-G]  (value not drawn)
SH-J22a  NPB02SVFN-RC  [NPB02SVFN-RC]
SH-J22b  NPB02SVFN-RC  [NPB02SVFN-RC]
SH-J22c  NPB02SVFN-RC  [NPB02SVFN-RC]
SH-J22d  NPB02SVFN-RC  [NPB02SVFN-RC]
SH-J22e  NPB02SVFN-RC  [NPB02SVFN-RC]
SH-J22f  NPB02SVFN-RC  [NPB02SVFN-RC]
SH-J22g  NPB02SVFN-RC  [NPB02SVFN-RC]
SH-J22h  NPB02SVFN-RC  [NPB02SVFN-RC]
SH-J22i  NPB02SVFN-RC  [NPB02SVFN-RC]
SH-J22j  NPB02SVFN-RC  [NPB02SVFN-RC]
SH-J22k  NPB02SVFN-RC  [NPB02SVFN-RC]
SH-J22l  NPB02SVFN-RC  [NPB02SVFN-RC]
SH-J22m  NPB02SVFN-RC  [NPB02SVFN-RC]
SH-J22n  NPB02SVFN-RC  [NPB02SVFN-RC]
SH-J22o  NPB02SVFN-RC  [NPB02SVFN-RC]
SH-J22p  NPB02SVFN-RC  [NPB02SVFN-RC]
SH-J22q  NPB02SVFN-RC  [NPB02SVFN-RC]
SH-J22r  NPB02SVFN-RC  [NPB02SVFN-RC]
SH-J22s  NPB02SVFN-RC  [NPB02SVFN-RC]
SH-J22t  NPB02SVFN-RC  [NPB02SVFN-RC]
SH-J22u  NPB02SVFN-RC  [NPB02SVFN-RC]
SH-J22v  NPB02SVFN-RC  [NPB02SVFN-RC]
SH-J22w  NPB02SVFN-RC  [NPB02SVFN-RC]
SH-J22x  NPB02SVFN-RC  [NPB02SVFN-RC]
SH-J24  969102-0000-DA  [SNT-100-BK-G]  (value not drawn)
SH-J27  969102-0000-DA  [SNT-100-BK-G]  (value not drawn)
ZZ1  This Assembly Note is for PCB labels only  [AssemblyNoteLabel]  (no BOM)
ZZ2  These assemblies are ESD sensitive, ESD precautions shall be observed.  [AssemblyNote]  (no BOM)
ZZ3  These assemblies must be clean and free from flux and all contaminants. Use of no clean flux is not acceptable.  [AssemblyNote]  (no BOM)
ZZ4  These assemblies must comply with workmanship standards IPC-A-610 Class 2, unless otherwise specified.  [AssemblyNote]  (no BOM)
ZZ5  Apply a thin layer of heatsink grease on top of U2 before installing heatsink  [AssemblyNote]  (no BOM)
ZZ6  When installing J7, J8, J11, and J12, do not install the bottom-side insulator. Nuts must contact bottom copper pads.  [AssemblyNote]  (no BOM)
ZZ7  When installing J1, J2, J18, and J20, solder AND bolt them  [AssemblyNote]  (no BOM)

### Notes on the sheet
- Variant
- Label Table
- Label Text
- COAX
- STP

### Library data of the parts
!PCB1 = PCB: Manufacturer: Any; PartNumber: SAT0084; SymbolCreator: a0412235
FID1-FID6 = Fiducial: Fiducial mark.  There is nothing to buy or mount.; SymbolCreator: codlsc
H1-H4 = NY PMS 440 0025 PH: Machine Screw, Round, #4-40 x 1/4, Nylon, Philips panhead; Manufacturer: B&F Fastener Supply; CompType: Hardware; SymbolCreator: codlsc; U/M: EA
H5-H8 = 1902C: Standoff, Hex, 1 1/16"L #4-40 Nylon; Manufacturer: Keystone; CompType: Hardware
H9 = V5583K: Heatsink, requires 2 M3 screw Mounting hole per rails; Manufacturer: Assman WSW; SymbolCreator: a0412235
H10-H13 = MPMS 003 0005 PH: MACHINE SCREW PAN PHILLIPS M3 10mm; Manufacturer: APM Hexseal; CompType: Hardware
H14-H17 = 1902C: ROUND SPACER M3 PVC 1.4MM; Manufacturer: Bivar; CompType: Hardware
H18 = MechPart: White silicone heatsink grease for U2; SymbolCreator: codlsc; CompType: Mechanical; U/M: EA
LBL1 = THT-14-423-10: Thermal Transfer Printable Labels, 0.650" W x 0.200" H - 10,000 per roll; Manufacturer: Brady; SymbolCreator: a0412235; CompType: Label
Logo1 = TI_Logo: Texas Instrument Corporate Signature; SymbolCreator: codlsc
SH-J3 SH-J5 SH-J8 SH-J10 SH-J13 SH-J16 SH-J19 SH-J22a SH-J22b SH-J22c SH-J22d SH-J22e SH-J22f SH-J22g SH-J22h SH-J22i SH-J22j SH-J22k SH-J22l SH-J22m SH-J22n SH-J22o SH-J22p SH-J22q SH-J22r SH-J22s SH-J22t SH-J22u SH-J22v SH-J22w SH-J22x = NPB02SVFN-RC: CONN JUMPER SHORTING 1.27MM GOLD; Manufacturer: Sullins Connector Solutions; Gender: Female Sockets; Number of Positions or Pins (Grid): 2 (1 x 2); Pitch: 0.050" (1.27mm)
SH-J21 SH-J24 SH-J27 = 969102-0000-DA: Shunt, 100mil, Gold plated, Black; Manufacturer: 3M; Alternate Manufacturer: Samtec; Value: 1x2; Note: You can "mate" this to a header by matching the designator.  i.e. use SH-J3 for header J3
ZZ1 = AssemblyNoteLabel: SymbolCreator: a0412235
ZZ2-ZZ7 = AssemblyNote: SymbolCreator: codlsc

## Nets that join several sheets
1V8: SAT0084E1-1_Power (R65.2 TP18.1 U14.2), SAT0084E1-1_Ser (11 pins), SAT0084E1-1_DeSer (12 pins)
3V3: SAT0084E1-1_Power (7 pins), SAT0084E1-1_Ser (7 pins), SAT0084E1-1_DeSer (10 pins), SAT0084E1-1_Backend (13 pins)
3V3_MCU: SAT0084E1-1_MCU (10 pins), SAT0084E1-1_Power (R45.2 R66.2 TP19.1)
8V: SAT0084E1-1_Power (5 pins), SAT0084E1-1_DeSer (C63.1 C64.1 L6.1)
GND: SAT0084E1-1_MCU (15 pins), SAT0084E1-1_Power (42 pins), SAT0084E1-1_Ser (42 pins), SAT0084E1-1_DeSer (50 pins), SAT0084E1-1_Backend (98 pins)
3V3_ENA: SAT0084E1-1_MCU (U6.17), SAT0084E1-1_Power (R57.2 U8.3)
3V3_PGD: SAT0084E1-1_MCU (U6.3), SAT0084E1-1_Power (R59.2 U8.9 U9.3)
8V_ENA: SAT0084E1-1_MCU (U6.9), SAT0084E1-1_Power (J24.1)
DESER_BISTEN: SAT0084E1-1_MCU (U6.23), SAT0084E1-1_DeSer (R19.1 U3.6)
DESER_GPI2: SAT0084E1-1_MCU (U6.31), SAT0084E1-1_DeSer (R20.1 TP54.1 U3.27)
DESER_GPI3: SAT0084E1-1_MCU (U6.32), SAT0084E1-1_DeSer (R54.1 TP55.1 U3.28)
DESER_I2C_SCL: SAT0084E1-1_Ser (J22.42), SAT0084E1-1_DeSer (R23.1 TP7.1 U3.2), SAT0084E1-1_Backend (U2.4)
DESER_I2C_SDA: SAT0084E1-1_Ser (J22.44), SAT0084E1-1_DeSer (R24.1 TP8.1 U3.1), SAT0084E1-1_Backend (U2.61)
DESER_I2S_BCK: SAT0084E1-1_Ser (J22.6), SAT0084E1-1_DeSer (U3.10), SAT0084E1-1_Backend (U1.13 U2.9)
DESER_I2S_DATA0: SAT0084E1-1_Ser (J22.10), SAT0084E1-1_DeSer (U3.11), SAT0084E1-1_Backend (J3.1 J8.1 J10.1)
DESER_I2S_DATA1: SAT0084E1-1_Ser (J22.12), SAT0084E1-1_DeSer (U3.12), SAT0084E1-1_Backend (J3.3 J8.3 J10.3)
DESER_I2S_DATA2: SAT0084E1-1_Ser (J22.14), SAT0084E1-1_DeSer (U3.13), SAT0084E1-1_Backend (J3.5 J8.5 J10.5)
DESER_I2S_DATA3: SAT0084E1-1_Ser (J22.16), SAT0084E1-1_DeSer (U3.14), SAT0084E1-1_Backend (J3.7 J8.7 J10.7)
DESER_I2S_DATA4: SAT0084E1-1_Ser (J22.18), SAT0084E1-1_DeSer (U3.15), SAT0084E1-1_Backend (J3.9 J8.9 J10.9)
DESER_I2S_DATA5: SAT0084E1-1_Ser (J22.20), SAT0084E1-1_DeSer (U3.16), SAT0084E1-1_Backend (J3.11 J8.11 J10.11)
DESER_I2S_DATA6: SAT0084E1-1_Ser (J22.22), SAT0084E1-1_DeSer (U3.18), SAT0084E1-1_Backend (J3.13 J8.13 J10.13)
DESER_I2S_DATA7: SAT0084E1-1_Ser (J22.24), SAT0084E1-1_DeSer (U3.19), SAT0084E1-1_Backend (J3.15 J8.15 J10.15)
DESER_I2S_LRCK: SAT0084E1-1_Ser (J22.4), SAT0084E1-1_DeSer (U3.9), SAT0084E1-1_Backend (U1.15 U2.19)
DESER_I2S_SCK: SAT0084E1-1_Ser (J22.2), SAT0084E1-1_DeSer (U3.8)
DESER_LOCK: SAT0084E1-1_MCU (U6.29), SAT0084E1-1_DeSer (R35.2 U3.48)
DESER_OEN: SAT0084E1-1_MCU (U6.24), SAT0084E1-1_DeSer (U3.5)
DESER_OSS_SEL: SAT0084E1-1_MCU (U6.25), SAT0084E1-1_DeSer (U3.4)
DESER_PASS: SAT0084E1-1_MCU (U6.30), SAT0084E1-1_DeSer (R34.2 U3.47)
DESER_PDB: SAT0084E1-1_MCU (U6.12), SAT0084E1-1_DeSer (R25.1 U3.30)
PCM_DEMP: SAT0084E1-1_MCU (U6.28), SAT0084E1-1_Backend (R5.2 U1.10)
PCM_FLT: SAT0084E1-1_MCU (U6.26), SAT0084E1-1_Backend (R4.2 U1.11)
PCM_FMT: SAT0084E1-1_MCU (U6.40), SAT0084E1-1_Backend (R6.2 U1.16)
PCM_MUTE_0: SAT0084E1-1_Ser (J22.28), SAT0084E1-1_DeSer (U3.21), SAT0084E1-1_Backend (J5.1)
PCM_MUTE_1: SAT0084E1-1_Ser (J22.30), SAT0084E1-1_DeSer (U3.22), SAT0084E1-1_Backend (J5.3)
PCM_MUTE_2: SAT0084E1-1_Ser (J22.32), SAT0084E1-1_DeSer (U3.23), SAT0084E1-1_Backend (J5.5)
PCM_MUTE_3: SAT0084E1-1_Ser (J22.34), SAT0084E1-1_DeSer (U3.24), SAT0084E1-1_Backend (J5.7)
PoC: SAT0084E1-1_Ser (L18.1 L20.5 R86.2), SAT0084E1-1_DeSer (6 pins)
SER_CLIP_OTW: SAT0084E1-1_MCU (U6.7), SAT0084E1-1_Ser (J22.37 U10.17)
SER_FAULT: SAT0084E1-1_MCU (U6.6), SAT0084E1-1_Ser (J22.35 U10.18)
SER_GPO2: SAT0084E1-1_MCU (U6.8), SAT0084E1-1_Ser (R2.2 TP38.1 U10.16)
SER_GPO3: SAT0084E1-1_MCU (U6.27), SAT0084E1-1_Ser (R1.2 TP37.1 U10.15)
SER_I2C_SCL: SAT0084E1-1_MCU (U6.11), SAT0084E1-1_Ser (J22.41 R72.1 TP23.1 U10.4)
SER_I2C_SDA: SAT0084E1-1_MCU (U6.10), SAT0084E1-1_Ser (J22.43 R73.1 TP24.1 U10.5)
SER_PDB: SAT0084E1-1_MCU (U6.16), SAT0084E1-1_Ser (R74.1 U10.9)
TAS_CLIP_OTW: SAT0084E1-1_Ser (J22.38), SAT0084E1-1_DeSer (U3.26), SAT0084E1-1_Backend (R21.1 TP5.1 U2.6)
TAS_FAULT: SAT0084E1-1_Ser (J22.36), SAT0084E1-1_DeSer (U3.25), SAT0084E1-1_Backend (R22.1 TP6.1 U2.62)
TAS_STANDBY: SAT0084E1-1_MCU (U6.15), SAT0084E1-1_Backend (R10.1 U2.3)

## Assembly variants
COAX: not fitted C84 C85 C109 C110 C111 C124 C125 C129 FID1 FID2 FID3 FID4 FID5 FID6 R26 R33 R37 R93 R95 U4 U5 U11 U12
STP: not fitted C82 C86 C109 C110 C111 C122 C126 C129 FID1 FID2 FID3 FID4 FID5 FID6 R26 R31 R88 U4 U5 U11 U12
